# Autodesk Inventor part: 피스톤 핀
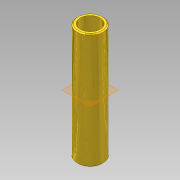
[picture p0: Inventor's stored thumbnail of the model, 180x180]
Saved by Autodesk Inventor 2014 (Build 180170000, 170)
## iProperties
Manager: KYOUNG IL JANG
Company: 한국ATC센터
Created: 2012-10
Part Number: 피스톤 핀
Document SubType Name: Modeling
Density: 1 g/cm^3
Checked By: KYOUNG IL JANG
Vendor: CBT Solutions
Designer: KYOUNG IL JANG
Material: Generic
Appearance: _시험_금속성 금색
Author: KYOUNG IL JANG
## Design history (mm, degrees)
sketch "스케치1"
  geometry: C1 r 6.5 at (0, 0); C2 r 5 at (0, 0); 1 further point
  constraints: 2 centre point, 2 coincident
  dimensions: "d0" = 13 diameter of C1; "d1" = 1.5 radial gap between concentric circles of C1 C2
extrude "돌출1" new body sketch "스케치1" stored distance "d2" = 58; taper "d3" = 0 deg
chamfer "모따기1" distance "d4" = 0.5; stored, may be unused: second distance "d5" = 2, angle "d6" = 45 deg
node "솔리드1"
